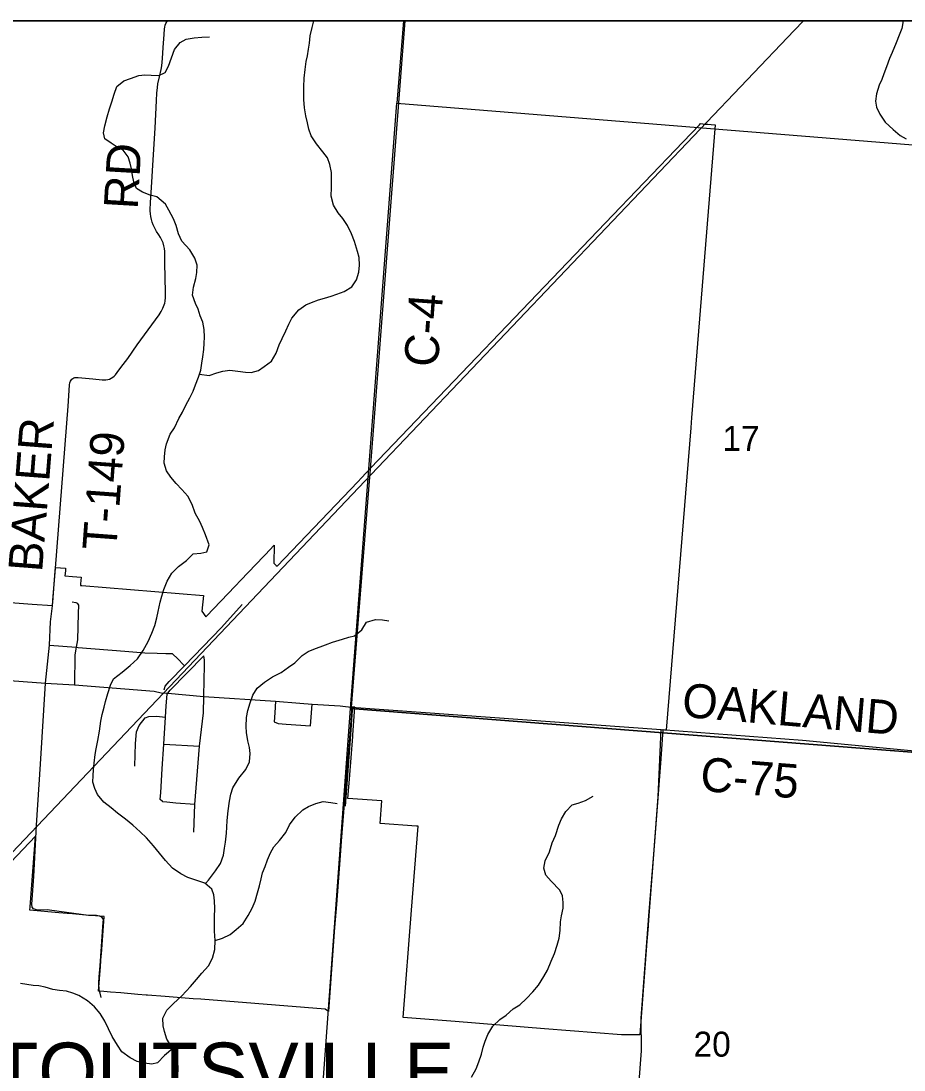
# Model space of a CAD drawing. Extents: x 0 to 42.5, y 0 to 22.
# Drawn here: x 5.71 to 6.449, y 20.022 to 20.9 of the extents above; entities that cross this region are included whole.
import ezdxf

# ---------------------------------------------------------------- set-up
doc = ezdxf.new("R2010")
doc.units = 0
for name, color, linetype in [('Default', 7, 'Continuous'), ('GM_X_City_Street', 7, 'Continuous'), ('GM_X_Corporation', 7, 'Continuous'), ('GM_X_Corporation_Text', 7, 'Continuous'), ('GM_X_County_Road', 7, 'Continuous'), ('GM_X_County_Road_Text', 7, 'Continuous'), ('GM_X_Interchange_Ramps', 7, 'Continuous'), ('GM_X_Major_River', 7, 'Continuous'), ('GM_X_Minor_River', 7, 'Continuous'), ('GM_X_Rail_Line', 7, 'Continuous'), ('GM_X_Section', 7, 'Continuous'), ('GM_X_Section_Text', 7, 'Continuous'), ('GM_X_Township_Road', 7, 'Continuous'), ('GM_X_Township_Road_Text', 7, 'Continuous'), ('SH_Cut_Line', 7, 'Continuous'), ('SH_Data', 7, 'Continuous')]:
    doc.layers.add(name, color=color, linetype=linetype)

msp = doc.modelspace()

# ---------------------------------------------------------------- linework, layer by layer
at = {"layer": 'Default'}
msp.add_lwpolyline([(6.56263, 20.9), (6.03047, 20.9), (6.02492, 20.83132), (6.5536, 20.78842)], close=True, dxfattribs=at)
at = {"layer": 'GM_X_City_Street'}
for p, q in [((5.95271, 20.31013), (5.95398, 20.32846)), ((5.82968, 20.29495), (5.85955, 20.29316))]:
    msp.add_line(p, q, dxfattribs=at)
for points in [[(5.72266, 20.21614), (5.72327, 20.22701), (5.7265, 20.27816), (5.73081, 20.34586), (5.73414, 20.37759), (5.73503, 20.3972), (5.73664, 20.41049)], [(5.75303, 20.41388), (5.75608, 20.41341), (5.75724, 20.4129), (5.75841, 20.41107), (5.75807, 20.40422), (5.75746, 20.38224), (5.75636, 20.37592), (5.75526, 20.36963), (5.75511, 20.3445)], [(5.83002, 20.34022), (5.83092, 20.34351), (5.83441, 20.34739), (5.84725, 20.36044), (5.87812, 20.39242), (5.8954, 20.41169)], [(5.73414, 20.37759), (5.75636, 20.37592), (5.75819, 20.37579), (5.79727, 20.3727)], [(5.79727, 20.3727), (5.81389, 20.37139), (5.82415, 20.371), (5.83152, 20.3708), (5.8369, 20.3707), (5.83799, 20.36961), (5.84078, 20.36712), (5.84725, 20.36044)], [(5.83178, 20.32688), (5.83251, 20.33674), (5.83304, 20.3374), (5.835, 20.33992), (5.86318, 20.36871)], [(5.85491, 20.22113), (5.85579, 20.24435), (5.85955, 20.29316), (5.86299, 20.3212), (5.86327, 20.33478), (5.86328, 20.33524), (5.86388, 20.36084), (5.86378, 20.36502), (5.86318, 20.36871)], [(5.92331, 20.33097), (5.92276, 20.32109), (5.92223, 20.31343)], [(5.82872, 20.24696), (5.8267, 20.24847), (5.82729, 20.25435), (5.82846, 20.27434), (5.82968, 20.29495), (5.83107, 20.31746), (5.83178, 20.32688)], [(5.98194, 20.24304), (5.98625, 20.30281), (5.98783, 20.32337), (5.98697, 20.32584)], [(5.80547, 20.27632), (5.8062, 20.29543), (5.80694, 20.30528), (5.80929, 20.31042), (5.81429, 20.31689), (5.81737, 20.31806), (5.8237, 20.31826), (5.83107, 20.31746)], [(5.92223, 20.31343), (5.92539, 20.31223), (5.93214, 20.31171), (5.95271, 20.31013)], [(5.85579, 20.24435), (5.83993, 20.24553), (5.83229, 20.24641), (5.82905, 20.24671), (5.82872, 20.24696)], [(5.77726, 20.08285), (5.77651, 20.08639), (5.77576, 20.08911), (5.7753, 20.09514), (5.7756, 20.10027), (5.77666, 20.10947), (5.77908, 20.14598), (5.77922, 20.14809), (5.77817, 20.14975), (5.77681, 20.15066), (5.7735, 20.15156), (5.76686, 20.15156), (5.74213, 20.15473), (5.73202, 20.15609), (5.72418, 20.15594), (5.72071, 20.15715), (5.71965, 20.1585), (5.7192, 20.16107), (5.72086, 20.184), (5.72266, 20.21614)]]:
    msp.add_lwpolyline(points, dxfattribs=at)
at = {"layer": 'GM_X_Corporation'}
msp.add_lwpolyline([(5.70153, 20.41346), (5.71947, 20.41207), (5.73663, 20.41075), (5.73687, 20.41381), (5.73803, 20.42869), (5.7386, 20.43606), (5.73889, 20.43973), (5.73913, 20.44276), (5.74761, 20.44203), (5.74742, 20.43996), (5.74705, 20.43572), (5.75338, 20.43518), (5.76051, 20.43458), (5.76008, 20.42888), (5.76, 20.42774), (5.76111, 20.4277), (5.86298, 20.41928), (5.86173, 20.40621), (5.86507, 20.40137), (5.86557, 20.40189), (5.88951, 20.42705), (5.8898, 20.42736), (5.89411, 20.43189), (5.9135, 20.45226), (5.91458, 20.45339), (5.92212, 20.46131), (5.92193, 20.44639), (5.92395, 20.44447), (5.92477, 20.4437), (5.99213, 20.51447), (5.99515, 20.51764), (6.0032, 20.52612), (6.19935, 20.73083), (6.26467, 20.79901), (6.27817, 20.81309), (6.27915, 20.81411), (6.28288, 20.81379), (6.28521, 20.81359), (6.2881, 20.81334), (6.29126, 20.81307), (6.27154, 20.56781), (6.27124, 20.56412), (6.27088, 20.55964), (6.25037, 20.30654), (6.24881, 20.30666), (6.24792, 20.30674), (6.24754, 20.30677), (6.24572, 20.28262), (6.2427, 20.2425), (6.23584, 20.15155), (6.23523, 20.14337), (6.23517, 20.14269), (6.23422, 20.13008), (6.22831, 20.05163), (6.21278, 20.05155), (6.14833, 20.05673), (6.07365, 20.06273), (6.03018, 20.06622), (6.03708, 20.15596), (6.04273, 20.22619), (6.04136, 20.22629), (6.01078, 20.22852), (6.01227, 20.2474), (5.98394, 20.24948), (5.98521, 20.26562), (5.98803, 20.30124), (5.98813, 20.30256), (5.98982, 20.32594), (5.98718, 20.32612), (5.98573, 20.30721), (5.9824, 20.26567), (5.97824, 20.21366), (5.97733, 20.20159), (5.97426, 20.16078), (5.97281, 20.14154), (5.96775, 20.07124), (5.96483, 20.07324), (5.906, 20.07783), (5.86092, 20.08134), (5.85431, 20.08186), (5.83082, 20.08368), (5.81608, 20.08483), (5.81511, 20.08491), (5.80797, 20.08551), (5.79381, 20.0867), (5.78518, 20.08742), (5.77966, 20.08788), (5.77514, 20.08826), (5.77593, 20.09842), (5.77675, 20.10881), (5.77744, 20.11772), (5.77755, 20.11919), (5.78, 20.15057), (5.7691, 20.15151), (5.76443, 20.1519), (5.75331, 20.15287), (5.74886, 20.15326), (5.7419, 20.15383), (5.71772, 20.15582), (5.71793, 20.15865), (5.72239, 20.21799), (5.62902, 20.11961)], dxfattribs=at)
at = {"layer": 'GM_X_County_Road'}
msp.add_line((5.98697, 20.32584), (6.00203, 20.51495), dxfattribs=at)
for points in [[(6.00203, 20.51495), (6.00254, 20.52142), (6.03181, 20.9)], [(5.56596, 20.35703), (5.57381, 20.35696), (5.58125, 20.35675), (5.59211, 20.35615), (5.73081, 20.34586), (5.75511, 20.3445), (5.82184, 20.33927), (5.82753, 20.33791), (5.83304, 20.3374), (5.86327, 20.33478), (5.92331, 20.33097), (5.94373, 20.32919), (5.95398, 20.32846), (5.97736, 20.32682), (5.98191, 20.32636)], [(5.98191, 20.32636), (5.98697, 20.32584), (6.24611, 20.30724)], [(6.24611, 20.30724), (6.36433, 20.29821), (6.49054, 20.28633), (6.51108, 20.28549), (6.60098, 20.27717), (6.97295, 20.24169), (7.0285, 20.23638), (7.37397, 20.20518), (7.74166, 20.17491), (7.77547, 20.17179)]]:
    msp.add_lwpolyline(points, dxfattribs=at)
at = {"layer": 'GM_X_Interchange_Ramps'}
msp.add_lwpolyline([(8.59772, 20.9), (5.60957, 20.9), (5.60252, 20.8068), (5.56586, 20.35729), (5.56563, 20.35496), (5.56474, 20.34561), (5.54606, 20.11658), (5.53536, 19.98472), (5.52526, 19.85376), (5.5156, 19.73605), (5.51061, 19.66936), (5.50057, 19.55251), (5.48884, 19.405)], dxfattribs=at)
at = {"layer": 'GM_X_Major_River'}
msp.add_lwpolyline([(6.44866, 20.9), (6.44753, 20.89359), (6.44523, 20.88809), (6.44292, 20.88184), (6.43947, 20.8735), (6.43716, 20.86857), (6.43466, 20.86155), (6.43255, 20.85568), (6.43082, 20.85094), (6.42852, 20.8462), (6.42639, 20.83899), (6.42541, 20.83292), (6.42634, 20.82798), (6.42914, 20.82189), (6.43366, 20.81541), (6.44026, 20.8093), (6.4463, 20.80415), (6.45121, 20.80128)], dxfattribs=at)
at = {"layer": 'GM_X_Minor_River'}
for points in [[(5.85965, 20.60458), (5.86771, 20.60331), (5.87418, 20.60552), (5.87932, 20.60699), (5.88502, 20.60788), (5.89164, 20.60704), (5.89827, 20.60602), (5.903, 20.60578), (5.90909, 20.60742), (5.91387, 20.61098), (5.91999, 20.61547), (5.92386, 20.62208), (5.92641, 20.62908), (5.92893, 20.63438), (5.93185, 20.6408), (5.93457, 20.64628), (5.93709, 20.6512), (5.94286, 20.65816), (5.9486, 20.66247), (5.95355, 20.66432), (5.95927, 20.66654), (5.9644, 20.668), (5.96992, 20.66984), (5.97468, 20.67131), (5.98077, 20.67352), (5.98708, 20.67763), (5.99112, 20.68348), (5.99309, 20.68973), (5.99354, 20.6958), (5.99324, 20.70208), (5.99197, 20.70722), (5.98941, 20.71542), (5.98683, 20.72191), (5.98369, 20.72897), (5.97959, 20.73472), (5.97566, 20.73951), (5.97194, 20.74582), (5.96995, 20.75344), (5.97022, 20.76066), (5.97029, 20.76674), (5.97018, 20.7732), (5.96874, 20.77987), (5.96672, 20.78559), (5.96299, 20.79057), (5.95757, 20.79728), (5.95309, 20.80398), (5.95126, 20.80951), (5.95019, 20.81484), (5.94874, 20.82075), (5.94768, 20.82722), (5.947, 20.83425), (5.94687, 20.83901), (5.94713, 20.84489), (5.9474, 20.85211), (5.94805, 20.85932), (5.94908, 20.86615), (5.95008, 20.87089), (5.95091, 20.87639), (5.95172, 20.88132), (5.95236, 20.88759), (5.95396, 20.8946), (5.95528, 20.9)], [(5.83208, 20.52352), (5.83007, 20.53), (5.83051, 20.53532), (5.83096, 20.5412), (5.83216, 20.54613), (5.8351, 20.55427), (5.83876, 20.55955), (5.84226, 20.5673), (5.84536, 20.57259), (5.84827, 20.57864), (5.85157, 20.58468), (5.85447, 20.59016), (5.85643, 20.59546), (5.85878, 20.60208), (5.86075, 20.60776), (5.86176, 20.61364), (5.86258, 20.61895), (5.86323, 20.62521), (5.86366, 20.63034), (5.86372, 20.63547), (5.86361, 20.64174), (5.86235, 20.64802), (5.86033, 20.65318), (5.8585, 20.6589), (5.85628, 20.66367), (5.85371, 20.67054), (5.85454, 20.67718), (5.85652, 20.68457), (5.85753, 20.6895), (5.8576, 20.69577), (5.85577, 20.70149), (5.8515, 20.70856), (5.84494, 20.71586), (5.84217, 20.72178), (5.84017, 20.72883), (5.83777, 20.73437), (5.83387, 20.74163), (5.83109, 20.74679), (5.82395, 20.75276), (5.81828, 20.75415), (5.81205, 20.75669), (5.80697, 20.75978), (5.80476, 20.76532), (5.80349, 20.77065), (5.80261, 20.77636), (5.80172, 20.78112), (5.79988, 20.78627), (5.79578, 20.79183), (5.79069, 20.79454), (5.7858, 20.79764), (5.78053, 20.80149), (5.77926, 20.80645), (5.78047, 20.81213), (5.78227, 20.8199), (5.78443, 20.82653), (5.78639, 20.8324), (5.78817, 20.83865), (5.79052, 20.84528), (5.79627, 20.84996), (5.80198, 20.8518), (5.80902, 20.85438), (5.81396, 20.8549), (5.81926, 20.85465), (5.82571, 20.85439), (5.83085, 20.8568), (5.83376, 20.86228), (5.83612, 20.8691), (5.83866, 20.8761), (5.84347, 20.88194), (5.84862, 20.88492), (5.85527, 20.8858), (5.86153, 20.88649), (5.86817, 20.8868)], [(5.84152, 20.0161), (5.84181, 20.02446), (5.84112, 20.03055), (5.83987, 20.03664), (5.83558, 20.04277), (5.83223, 20.04812), (5.83041, 20.05442), (5.82913, 20.05918), (5.82902, 20.06564), (5.83232, 20.07226), (5.83788, 20.07789), (5.84478, 20.08428), (5.85208, 20.09199), (5.85727, 20.09801), (5.8615, 20.1031), (5.86707, 20.1095), (5.87056, 20.11592), (5.87254, 20.12293), (5.87281, 20.13052), (5.87234, 20.13851), (5.87221, 20.14345), (5.8721, 20.15048), (5.87237, 20.15732), (5.87225, 20.16378), (5.87155, 20.16873), (5.8699, 20.1735), (5.86427, 20.1785), (5.85748, 20.18085), (5.84992, 20.18341), (5.84408, 20.18632), (5.83712, 20.19115), (5.83132, 20.19748), (5.82608, 20.20362), (5.82122, 20.20975), (5.81542, 20.21646), (5.80998, 20.22146), (5.80379, 20.22704), (5.79759, 20.23205), (5.79102, 20.23725), (5.78576, 20.24149), (5.77956, 20.24631), (5.77432, 20.25263), (5.77192, 20.25779), (5.77027, 20.26294), (5.77053, 20.26864), (5.77096, 20.27338), (5.7714, 20.27889), (5.77225, 20.2861), (5.77325, 20.29103), (5.77466, 20.29804), (5.77589, 20.30582), (5.77712, 20.31398), (5.77814, 20.31967), (5.77992, 20.32592), (5.78092, 20.33066), (5.78289, 20.33728), (5.78506, 20.3441), (5.78777, 20.34939), (5.79505, 20.3552), (5.80174, 20.36064), (5.80769, 20.36627), (5.81251, 20.37325), (5.81677, 20.3808), (5.81969, 20.38761), (5.82223, 20.39405), (5.82383, 20.40068), (5.82502, 20.4058), (5.82682, 20.41357), (5.82802, 20.41868), (5.82979, 20.42436), (5.83271, 20.43136), (5.83658, 20.43797), (5.84196, 20.44342), (5.84865, 20.44848), (5.85441, 20.45412), (5.86067, 20.45462), (5.8658, 20.4557), (5.86777, 20.46176), (5.86464, 20.47015), (5.86205, 20.47607), (5.85984, 20.48104), (5.85594, 20.48811), (5.85356, 20.49536), (5.84985, 20.50224), (5.84498, 20.50799), (5.84011, 20.51298), (5.83563, 20.51835), (5.83208, 20.52352)], [(5.86468, 20.17814), (5.86734, 20.18113), (5.87311, 20.18885), (5.87736, 20.19508), (5.87971, 20.20189), (5.88073, 20.20796), (5.88155, 20.21289), (5.8822, 20.22048), (5.88245, 20.22542), (5.88271, 20.23093), (5.88356, 20.23909), (5.88479, 20.24706), (5.886, 20.25293), (5.88758, 20.25843), (5.8926, 20.26635), (5.89837, 20.2737), (5.90148, 20.28013), (5.90213, 20.28715), (5.90143, 20.2921), (5.90017, 20.29762), (5.89892, 20.30466), (5.8986, 20.30961), (5.89907, 20.3172), (5.90008, 20.32289), (5.90205, 20.32933), (5.90441, 20.33576), (5.90789, 20.34162), (5.91401, 20.34687), (5.92089, 20.35117), (5.92795, 20.35489), (5.93426, 20.35938), (5.93942, 20.36293), (5.94556, 20.36914), (5.95052, 20.37231), (5.95529, 20.37435), (5.96519, 20.37804), (5.97109, 20.38007), (5.97927, 20.38264), (5.98461, 20.38448), (5.98936, 20.38557), (5.99567, 20.39063), (5.99954, 20.39686), (6.00696, 20.39925), (6.01283, 20.3988), (6.01813, 20.39798)], [(6.08743, 20.01608), (6.09112, 20.02307), (6.09346, 20.02912), (6.09562, 20.03537), (6.09721, 20.04124), (6.09878, 20.04635), (6.10093, 20.05184), (6.10519, 20.05901), (6.11094, 20.06446), (6.11629, 20.06801), (6.12223, 20.07327), (6.12777, 20.07682), (6.13352, 20.08207), (6.1387, 20.08753), (6.14351, 20.09318), (6.14776, 20.10054), (6.15105, 20.10563), (6.15417, 20.11339), (6.1569, 20.11982), (6.15907, 20.12664), (6.16065, 20.13251), (6.16167, 20.13896), (6.16195, 20.14618), (6.16257, 20.15111), (6.16398, 20.15756), (6.16422, 20.16249), (6.16353, 20.16801), (6.16131, 20.17278), (6.154, 20.18028), (6.14951, 20.18526), (6.14787, 20.19098), (6.14889, 20.19724), (6.15277, 20.2048), (6.15494, 20.21219), (6.15767, 20.21843), (6.16043, 20.22714), (6.16257, 20.23243), (6.16625, 20.23847), (6.17162, 20.24411), (6.17657, 20.24558), (6.18266, 20.2476), (6.18915, 20.25133)], [(5.8728, 20.13068), (5.87891, 20.13255), (5.88539, 20.13552), (5.89037, 20.13983), (5.8963, 20.1449), (5.90036, 20.1515), (5.90385, 20.15774), (5.90638, 20.16341), (5.90816, 20.17042), (5.90994, 20.17629), (5.91134, 20.18217), (5.91253, 20.18709), (5.91468, 20.19258), (5.91664, 20.19807), (5.91898, 20.20393), (5.92188, 20.20884), (5.9265, 20.21411), (5.93188, 20.22089), (5.93499, 20.22732), (5.93962, 20.23373), (5.94614, 20.23993), (5.95091, 20.24272), (5.95701, 20.24532), (5.96328, 20.24677), (5.96953, 20.24613), (5.97502, 20.24531)], [(5.8373, 20.04031), (5.83036, 20.03428), (5.8246, 20.02807), (5.81985, 20.02698), (5.8136, 20.02781), (5.80736, 20.0294), (5.80152, 20.03231), (5.79475, 20.03751), (5.79103, 20.04307), (5.78656, 20.05033), (5.78045, 20.06294), (5.77655, 20.06944), (5.77187, 20.07501), (5.76586, 20.0802), (5.75871, 20.08465), (5.75362, 20.08661), (5.74832, 20.08818), (5.74245, 20.08882), (5.73696, 20.08945), (5.73035, 20.09142), (5.72525, 20.09262), (5.72051, 20.09305), (5.71502, 20.09387), (5.70972, 20.09469)]]:
    msp.add_lwpolyline(points, dxfattribs=at)
at = {"layer": 'GM_X_Rail_Line'}
msp.add_lwpolyline([(5.54064, 20.03224), (5.69761, 20.19849), (6.00325, 20.52048), (6.35749, 20.89191), (6.36519, 20.9)], dxfattribs=at)
at = {"layer": 'GM_X_Section'}
for points in [[(6.02492, 20.83132), (6.5536, 20.78842), (6.51305, 20.28378), (5.98607, 20.32479)], [(6.51305, 20.28378), (6.47172, 19.77233), (5.94892, 19.81768), (5.98607, 20.32479)]]:
    msp.add_lwpolyline(points, close=True, dxfattribs=at)
at = {"layer": 'GM_X_Township_Road'}
for points in [[(5.73919, 20.44216), (5.74963, 20.57765), (5.75059, 20.5909), (5.75093, 20.59556), (5.75118, 20.59712), (5.75169, 20.59859), (5.75218, 20.5994), (5.75281, 20.60015), (5.75364, 20.60085), (5.75452, 20.60129), (5.75545, 20.60159), (5.7565, 20.60171), (5.75815, 20.60171), (5.76125, 20.60144), (5.77045, 20.60045), (5.77819, 20.59985), (5.7813, 20.59986), (5.78284, 20.60004), (5.78435, 20.60041), (5.78576, 20.60103), (5.78706, 20.60185), (5.78823, 20.60286), (5.78927, 20.60401), (5.79209, 20.60773), (5.79582, 20.61269), (5.79958, 20.61763), (5.8076, 20.62906), (5.82577, 20.65424), (5.82748, 20.65684), (5.82894, 20.65957), (5.82956, 20.661), (5.83009, 20.66246), (5.83052, 20.66395), (5.83084, 20.66546), (5.83118, 20.66854), (5.83121, 20.6732), (5.83062, 20.69744), (5.83063, 20.70458), (5.83062, 20.70707), (5.83038, 20.70954), (5.8299, 20.71198), (5.82919, 20.71437), (5.82825, 20.71668), (5.8271, 20.71888), (5.82575, 20.72097), (5.82377, 20.72398), (5.82198, 20.7271), (5.82094, 20.72931), (5.82008, 20.7316), (5.81939, 20.73395), (5.81889, 20.73634), (5.81857, 20.73876), (5.81844, 20.7412), (5.81849, 20.74204), (5.81878, 20.74821), (5.81956, 20.76061), (5.82092, 20.78385), (5.82244, 20.8102), (5.8236, 20.8334), (5.82394, 20.83965), (5.8244, 20.84428), (5.82486, 20.84734), (5.82621, 20.85339), (5.82766, 20.85942), (5.82819, 20.86247), (5.82879, 20.86864), (5.82936, 20.87794), (5.82996, 20.88878), (5.8304, 20.89341), (5.83065, 20.89494), (5.83105, 20.89644), (5.83162, 20.89788), (5.83242, 20.8992), (5.8331, 20.9)], [(5.73664, 20.41049), (5.73697, 20.41513), (5.73919, 20.44216)], [(6.18413, 19.49975), (6.18925, 19.5258), (6.19935, 19.65277), (6.20314, 19.69922), (6.2113, 19.79656), (6.22971, 20.03831), (6.22937, 20.0656), (6.23566, 20.15108), (6.2399, 20.20268), (6.24355, 20.25066), (6.24611, 20.30724)]]:
    msp.add_lwpolyline(points, dxfattribs=at)
at = {"layer": 'SH_Cut_Line'}
msp.add_lwpolyline([(8.9, 20.9), (5.60957, 20.9), (5.60252, 20.8068), (5.56586, 20.35729), (5.56563, 20.35496), (5.56474, 20.34561), (5.54606, 20.11658), (5.53536, 19.98472), (5.52526, 19.85376), (5.5156, 19.73605), (5.51061, 19.66936), (5.50057, 19.55251), (5.48884, 19.405)], dxfattribs=at)
at = {"layer": 'SH_Data'}
msp.add_line((2.1, 20.9), (8.9, 20.9), dxfattribs=at)

# ---------------------------------------------------------------- texts
at = {"layer": 'GM_X_Corporation_Text'}
msp.add_text('STOUTSVILLE', height=0.0473485, rotation=0.00001, dxfattribs=at).set_placement((5.64379, 19.99777))
at = {"layer": 'GM_X_County_Road_Text'}
for s, rotation, p in [('C-4', 85.88145, (6.05915, 20.6098)), ('OAKLAND', 355.13231, (6.26288, 20.31783)), ('C-75', 355.54865, (6.27817, 20.2558))]:
    msp.add_text(s, height=0.028409, rotation=rotation, dxfattribs=at).set_placement(p)
at = {"layer": 'GM_X_Section_Text'}
for s, p in [('17', (6.29742, 20.5403)), ('20', (6.27325, 20.03337))]:
    msp.add_text(s, height=0.020928, rotation=0.00001, dxfattribs=at).set_placement(p)
at = {"layer": 'GM_X_Township_Road_Text'}
for s, rotation, p in [('RD', 86.57733, (5.80785, 20.74204)), ('BAKER', 85.52347, (5.72788, 20.43835)), ('T-149', 85.79481, (5.78993, 20.45639))]:
    msp.add_text(s, height=0.028409, rotation=rotation, dxfattribs=at).set_placement(p)

doc.saveas('drawing.dxf')
